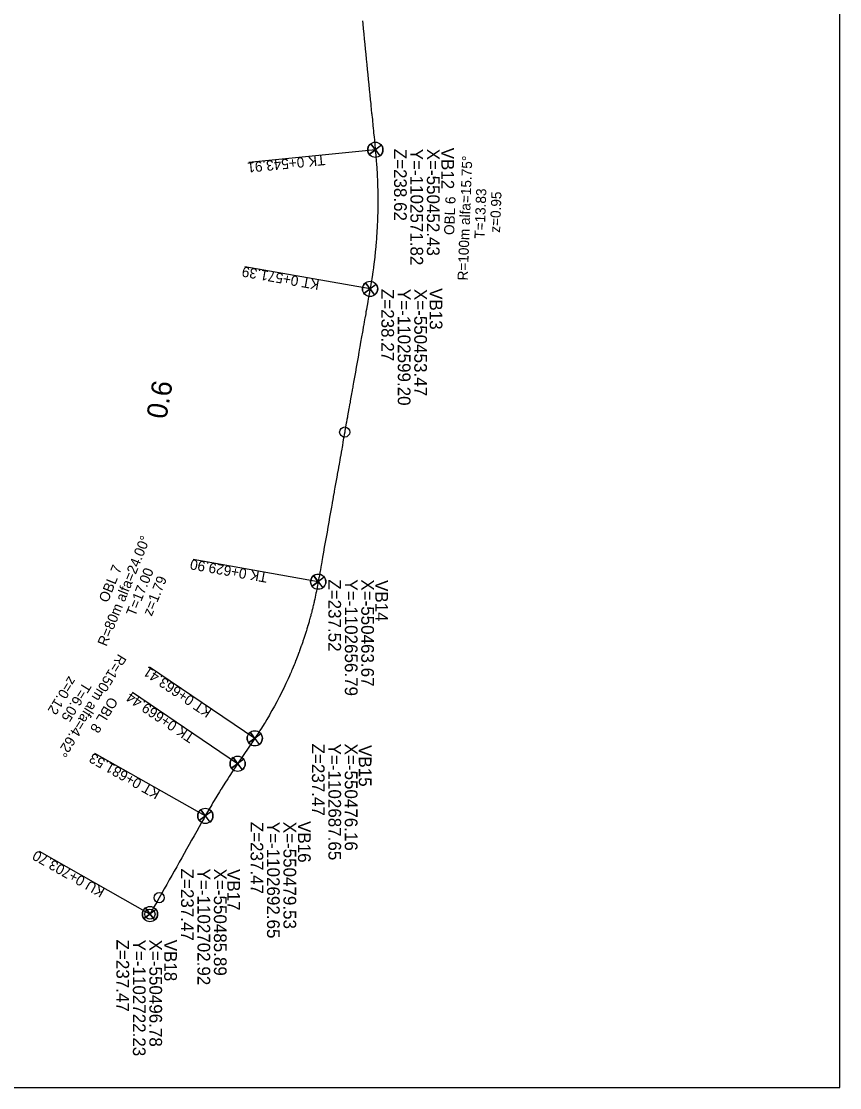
# Model space of a CAD drawing. Extents: x -583517 to -548566, y -1166112 to -1101582.
# Drawn here: x -550522.1 to -550361.1, y -1102756.4 to -1102546.5 of the extents above; entities that cross this region are included whole.
import ezdxf

# ---------------------------------------------------------------- set-up
doc = ezdxf.new("R2010")
doc.units = 0
for name, color, linetype in [('13', 7, 'Continuous'), ('59', 7, 'Continuous'), ('8', 7, 'Continuous'), ('Body pricny rez', 7, 'Continuous'), ('Rámy', 7, 'Continuous')]:
    doc.layers.add(name, color=color, linetype=linetype)

msp = doc.modelspace()

# ---------------------------------------------------------------- linework, layer by layer
at = {"layer": '13'}
for points in [[(-550452.43, -1102571.82), (-550477.31, -1102574.31)], [(-550453.47, -1102599.2), (-550478.09, -1102594.85)], [(-550463.67, -1102656.82), (-550488.29, -1102652.46)], [(-550476.16, -1102687.65), (-550496.87, -1102673.65)], [(-550479.53, -1102692.65), (-550500.25, -1102678.65)], [(-550485.89, -1102702.92), (-550507.66, -1102690.64)], [(-550496.78, -1102722.24), (-550518.55, -1102709.95)]]:
    msp.add_lwpolyline(points, dxfattribs=at)
at = {"layer": '8'}
for p, q in [((-550451.23, -1102570.93), (-550453.64, -1102572.72)), ((-550453.33, -1102570.62), (-550451.54, -1102573.03)), ((-550452.43, -1102571.82), (-550453.33, -1102570.62)), ((-550452.43, -1102571.82), (-550453.33, -1102570.62)), ((-550451.23, -1102570.93), (-550452.43, -1102571.82)), ((-550453.64, -1102572.72), (-550452.43, -1102571.82)), ((-550453.64, -1102572.72), (-550452.43, -1102571.82)), ((-550452.43, -1102571.82), (-550451.54, -1102573.03)), ((-550452.27, -1102598.31), (-550454.67, -1102600.1)), ((-550454.36, -1102598), (-550452.57, -1102600.41)), ((-550453.47, -1102599.2), (-550454.36, -1102598)), ((-550453.47, -1102599.2), (-550454.36, -1102598)), ((-550452.26, -1102598.31), (-550453.47, -1102599.2)), ((-550454.67, -1102600.1), (-550453.47, -1102599.2)), ((-550454.67, -1102600.1), (-550453.47, -1102599.2)), ((-550453.47, -1102599.2), (-550452.57, -1102600.41)), ((-550462.47, -1102655.92), (-550464.88, -1102657.71)), ((-550464.88, -1102657.71), (-550463.67, -1102656.82)), ((-550464.88, -1102657.71), (-550463.67, -1102656.82)), ((-550464.57, -1102655.61), (-550462.78, -1102658.02)), ((-550463.67, -1102656.82), (-550464.57, -1102655.61)), ((-550463.67, -1102656.82), (-550464.57, -1102655.61)), ((-550462.47, -1102655.92), (-550463.67, -1102656.82)), ((-550463.67, -1102656.82), (-550462.78, -1102658.02)), ((-550474.95, -1102686.76), (-550477.36, -1102688.54)), ((-550477.05, -1102686.45), (-550475.26, -1102688.85)), ((-550476.16, -1102687.65), (-550477.05, -1102686.45)), ((-550476.16, -1102687.65), (-550477.05, -1102686.45)), ((-550474.95, -1102686.75), (-550476.16, -1102687.65)), ((-550477.36, -1102688.55), (-550476.16, -1102687.65)), ((-550477.36, -1102688.55), (-550476.16, -1102687.65)), ((-550476.16, -1102687.65), (-550475.26, -1102688.85)), ((-550480.74, -1102693.54), (-550479.53, -1102692.65)), ((-550480.74, -1102693.54), (-550479.53, -1102692.65)), ((-550478.33, -1102691.75), (-550480.73, -1102693.54)), ((-550480.43, -1102691.44), (-550478.64, -1102693.85)), ((-550479.53, -1102692.65), (-550480.43, -1102691.44)), ((-550479.53, -1102692.65), (-550480.43, -1102691.44)), ((-550478.33, -1102691.75), (-550479.53, -1102692.65)), ((-550479.53, -1102692.65), (-550478.64, -1102693.85)), ((-550486.78, -1102701.72), (-550484.99, -1102704.13)), ((-550485.89, -1102702.92), (-550486.78, -1102701.72)), ((-550485.89, -1102702.92), (-550486.78, -1102701.72)), ((-550484.68, -1102702.03), (-550487.09, -1102703.82)), ((-550487.09, -1102703.82), (-550485.89, -1102702.92)), ((-550487.09, -1102703.82), (-550485.89, -1102702.92)), ((-550484.68, -1102702.03), (-550485.89, -1102702.92)), ((-550485.89, -1102702.92), (-550484.99, -1102704.13)), ((-550495.58, -1102721.34), (-550497.98, -1102723.13)), ((-550497.98, -1102723.13), (-550496.78, -1102722.24)), ((-550497.98, -1102723.13), (-550496.78, -1102722.24)), ((-550496.78, -1102722.24), (-550497.68, -1102721.03)), ((-550496.78, -1102722.24), (-550497.68, -1102721.03)), ((-550497.67, -1102721.03), (-550495.89, -1102723.44)), ((-550495.58, -1102721.34), (-550496.78, -1102722.24)), ((-550496.78, -1102722.24), (-550495.88, -1102723.44))]:
    msp.add_line(p, q, dxfattribs=at)
for centre in [(-550452.43, -1102571.82), (-550453.47, -1102599.2), (-550463.67, -1102656.82), (-550476.16, -1102687.65), (-550479.53, -1102692.65), (-550485.89, -1102702.92), (-550496.78, -1102722.24)]:
    msp.add_circle(centre, 1.5, dxfattribs=at)
for centre, start, end in [((-550452.43, -1102571.82), 126.6271, 216.6271), ((-550452.43, -1102571.82), 126.6271, 216.6271), ((-550452.43, -1102571.82), 306.6271, 36.6271), ((-550453.47, -1102599.2), 126.6271, 216.6271), ((-550453.47, -1102599.2), 126.6271, 216.6271), ((-550453.47, -1102599.2), 306.6271, 36.6271), ((-550463.67, -1102656.82), 126.6271, 216.6271), ((-550463.67, -1102656.82), 126.6271, 216.6271), ((-550463.67, -1102656.82), 306.6271, 36.6271), ((-550476.16, -1102687.65), 126.6271, 216.6271), ((-550476.16, -1102687.65), 126.6271, 216.6271), ((-550476.16, -1102687.65), 306.6271, 36.6271), ((-550479.53, -1102692.65), 126.6271, 216.6271), ((-550479.53, -1102692.65), 126.6271, 216.6271), ((-550479.53, -1102692.65), 306.6271, 36.6271), ((-550485.89, -1102702.92), 126.6271, 216.6271), ((-550485.89, -1102702.92), 126.6271, 216.6271), ((-550485.89, -1102702.92), 306.6271, 36.6271), ((-550496.78, -1102722.24), 126.6271, 216.6271), ((-550496.78, -1102722.24), 126.6271, 216.6271), ((-550496.78, -1102722.24), 306.6271, 36.6271)]:
    msp.add_arc(centre, 1.5, start, end, dxfattribs=at)
at = {"layer": 'Body pricny rez'}
msp.add_lwpolyline([(-550454.97, -1102546.43), (-550454.91, -1102547.04), (-550454.9, -1102547.17), (-550454.89, -1102547.19), (-550454.82, -1102547.9), (-550454.81, -1102548.04), (-550454.71, -1102549.03), (-550454.61, -1102550.03), (-550454.51, -1102551.02), (-550454.41, -1102552.02), (-550454.31, -1102553.01), (-550454.21, -1102554.01), (-550454.11, -1102555), (-550454.01, -1102556), (-550453.91, -1102556.99), (-550453.82, -1102557.99), (-550453.72, -1102558.98), (-550453.62, -1102559.98), (-550453.52, -1102560.97), (-550453.42, -1102561.97), (-550453.34, -1102562.73), (-550453.34, -1102562.75), (-550453.32, -1102562.96), (-550453.31, -1102563.05), (-550453.22, -1102563.96), (-550453.16, -1102564.58), (-550453.14, -1102564.79), (-550453.12, -1102564.95), (-550453.11, -1102565.09), (-550453.08, -1102565.3), (-550453.08, -1102565.36), (-550453.02, -1102565.95), (-550453, -1102566.1), (-550453, -1102566.14), (-550452.92, -1102566.91), (-550452.92, -1102566.94), (-550452.85, -1102567.69), (-550452.82, -1102567.94), (-550452.77, -1102568.47), (-550452.72, -1102568.93), (-550452.69, -1102569.25), (-550452.62, -1102569.93), (-550452.61, -1102570.02), (-550452.53, -1102570.8), (-550452.53, -1102570.83), (-550452.52, -1102570.92), (-550452.46, -1102571.58), (-550452.43, -1102571.82), (-550452.42, -1102571.92), (-550452.38, -1102572.36), (-550452.33, -1102572.91), (-550452.31, -1102573.14), (-550452.25, -1102573.91), (-550452.25, -1102573.91), (-550452.24, -1102573.93), (-550452.19, -1102574.69), (-550452.17, -1102574.91), (-550452.16, -1102575.06), (-550452.12, -1102575.65), (-550452.11, -1102575.84), (-550452.11, -1102575.9), (-550452.1, -1102576.04), (-550452.09, -1102576.19), (-550452.09, -1102576.22), (-550452.06, -1102576.72), (-550452.06, -1102576.9), (-550452.01, -1102577.9), (-550452, -1102578.15), (-550451.98, -1102578.9), (-550451.95, -1102579.9), (-550451.95, -1102580.26), (-550451.94, -1102580.9), (-550451.94, -1102581.9), (-550451.94, -1102582.38), (-550451.94, -1102582.71), (-550451.94, -1102582.9), (-550451.96, -1102583.9), (-550451.97, -1102584.49), (-550451.98, -1102584.62), (-550451.99, -1102584.9), (-550451.99, -1102585.06), (-550451.99, -1102585.06), (-550452.02, -1102585.9), (-550452.05, -1102586.61), (-550452.07, -1102586.9), (-550452.08, -1102587.19), (-550452.12, -1102587.8), (-550452.12, -1102587.9), (-550452.13, -1102588.01), (-550452.14, -1102588.1), (-550452.15, -1102588.3), (-550452.18, -1102588.72), (-550452.19, -1102588.89), (-550452.23, -1102589.47), (-550452.27, -1102589.89), (-550452.35, -1102590.82), (-550452.35, -1102590.89), (-550452.45, -1102591.88), (-550452.56, -1102592.88), (-550452.56, -1102592.93), (-550452.67, -1102593.87), (-550452.8, -1102594.86), (-550452.82, -1102595.03), (-550452.93, -1102595.85), (-550453.08, -1102596.84), (-550453.12, -1102597.12), (-550453.14, -1102597.21), (-550453.2, -1102597.63), (-550453.24, -1102597.83), (-550453.24, -1102597.87), (-550453.32, -1102598.35), (-550453.4, -1102598.82), (-550453.46, -1102599.17), (-550453.47, -1102599.2), (-550453.57, -1102599.8), (-550453.61, -1102599.99), (-550453.64, -1102600.19), (-550453.75, -1102600.79), (-550453.75, -1102600.81), (-550453.9, -1102601.63), (-550453.92, -1102601.77), (-550454.04, -1102602.45), (-550454.1, -1102602.76), (-550454.19, -1102603.27), (-550454.27, -1102603.74), (-550454.33, -1102604.09), (-550454.45, -1102604.73), (-550454.48, -1102604.9), (-550454.62, -1102605.71), (-550454.62, -1102605.72), (-550454.77, -1102606.54), (-550454.8, -1102606.69), (-550454.91, -1102607.36), (-550454.97, -1102607.68), (-550455.14, -1102608.66), (-550455.32, -1102609.65), (-550455.49, -1102610.63), (-550455.54, -1102610.88), (-550455.67, -1102611.62), (-550455.84, -1102612.6), (-550456.02, -1102613.59), (-550456.19, -1102614.57), (-550456.36, -1102615.56), (-550456.54, -1102616.54), (-550456.71, -1102617.53), (-550456.86, -1102618.33), (-550456.89, -1102618.51), (-550456.99, -1102619.06), (-550457.01, -1102619.19), (-550457.06, -1102619.5), (-550457.11, -1102619.79), (-550457.13, -1102619.9), (-550457.15, -1102619.98), (-550457.17, -1102620.09), (-550457.18, -1102620.15), (-550457.24, -1102620.48), (-550457.24, -1102620.52), (-550457.37, -1102621.25), (-550457.41, -1102621.46), (-550457.47, -1102621.8), (-550457.5, -1102621.98), (-550457.59, -1102622.45), (-550457.63, -1102622.71), (-550457.76, -1102623.43), (-550457.76, -1102623.44), (-550457.89, -1102624.17), (-550457.93, -1102624.42), (-550458.02, -1102624.9), (-550458.11, -1102625.4), (-550458.15, -1102625.63), (-550458.28, -1102626.36), (-550458.28, -1102626.39), (-550458.41, -1102627.09), (-550458.46, -1102627.37), (-550458.54, -1102627.82), (-550458.63, -1102628.36), (-550458.67, -1102628.55), (-550458.8, -1102629.28), (-550458.81, -1102629.34), (-550458.92, -1102630.01), (-550458.98, -1102630.33), (-550459.05, -1102630.74), (-550459.15, -1102631.31), (-550459.18, -1102631.47), (-550459.31, -1102632.2), (-550459.33, -1102632.3), (-550459.44, -1102632.93), (-550459.5, -1102633.28), (-550459.57, -1102633.66), (-550459.68, -1102634.27), (-550459.7, -1102634.39), (-550459.83, -1102635.12), (-550459.85, -1102635.25), (-550460.03, -1102636.23), (-550460.2, -1102637.22), (-550460.31, -1102637.86), (-550460.38, -1102638.2), (-550460.51, -1102638.99), (-550460.55, -1102639.19), (-550460.71, -1102640.08), (-550460.72, -1102640.17), (-550460.88, -1102641.05), (-550460.9, -1102641.16), (-550460.94, -1102641.37), (-550461, -1102641.75), (-550461.07, -1102642.14), (-550461.25, -1102643.13), (-550461.42, -1102644.11), (-550461.6, -1102645.1), (-550461.77, -1102646.08), (-550461.94, -1102647.07), (-550462.12, -1102648.05), (-550462.29, -1102649.04), (-550462.47, -1102650.02), (-550462.64, -1102651), (-550462.75, -1102651.64), (-550462.82, -1102651.99), (-550462.82, -1102652.03), (-550462.89, -1102652.43), (-550462.96, -1102652.82), (-550462.99, -1102652.97), (-550463.03, -1102653.21), (-550463.1, -1102653.61), (-550463.16, -1102653.92), (-550463.17, -1102653.96), (-550463.17, -1102654), (-550463.24, -1102654.39), (-550463.31, -1102654.79), (-550463.34, -1102654.94), (-550463.38, -1102655.15), (-550463.38, -1102655.18), (-550463.45, -1102655.57), (-550463.51, -1102655.93), (-550463.52, -1102655.97), (-550463.59, -1102656.36), (-550463.66, -1102656.75), (-550463.67, -1102656.82), (-550463.69, -1102656.91), (-550463.73, -1102657.15), (-550463.8, -1102657.54), (-550463.87, -1102657.9), (-550463.88, -1102657.93), (-550463.95, -1102658.33), (-550464.02, -1102658.64), (-550464.03, -1102658.72), (-550464.06, -1102658.88), (-550464.11, -1102659.11), (-550464.19, -1102659.5), (-550464.27, -1102659.86), (-550464.28, -1102659.89), (-550464.36, -1102660.28), (-550464.41, -1102660.47), (-550464.45, -1102660.67), (-550464.49, -1102660.83), (-550464.54, -1102661.06), (-550464.6, -1102661.32), (-550464.63, -1102661.45), (-550464.65, -1102661.52), (-550464.72, -1102661.8), (-550464.73, -1102661.84), (-550464.74, -1102661.91), (-550464.82, -1102662.23), (-550464.84, -1102662.28), (-550464.92, -1102662.61), (-550464.96, -1102662.77), (-550465.02, -1102663), (-550465.1, -1102663.28), (-550465.12, -1102663.39), (-550465.22, -1102663.74), (-550465.23, -1102663.77), (-550465.31, -1102664.08), (-550465.33, -1102664.16), (-550465.33, -1102664.16), (-550465.36, -1102664.27), (-550465.36, -1102664.27), (-550465.36, -1102664.27), (-550465.37, -1102664.28), (-550465.44, -1102664.54), (-550465.45, -1102664.57), (-550465.48, -1102664.71), (-550465.55, -1102664.93), (-550465.55, -1102664.94), (-550465.66, -1102665.31), (-550465.76, -1102665.67), (-550465.77, -1102665.7), (-550465.82, -1102665.87), (-550465.89, -1102666.08), (-550466, -1102666.46), (-550466.05, -1102666.62), (-550466.12, -1102666.84), (-550466.24, -1102667.22), (-550466.36, -1102667.58), (-550466.37, -1102667.6), (-550466.38, -1102667.64), (-550466.49, -1102667.98), (-550466.67, -1102668.52), (-550466.69, -1102668.57), (-550466.73, -1102668.7), (-550466.75, -1102668.74), (-550466.76, -1102668.79), (-550466.78, -1102668.83), (-550466.98, -1102669.41), (-550467, -1102669.47), (-550467.34, -1102670.41), (-550467.45, -1102670.71), (-550467.46, -1102670.74), (-550467.53, -1102670.93), (-550467.61, -1102671.16), (-550467.69, -1102671.35), (-550467.82, -1102671.69), (-550467.93, -1102671.98), (-550468.04, -1102672.25), (-550468.04, -1102672.26), (-550468.05, -1102672.28), (-550468.29, -1102672.89), (-550468.42, -1102673.21), (-550468.81, -1102674.13), (-550468.91, -1102674.36), (-550469.01, -1102674.61), (-550469.13, -1102674.87), (-550469.15, -1102674.91), (-550469.15, -1102674.92), (-550469.16, -1102674.94), (-550469.2, -1102675.05), (-550469.33, -1102675.33), (-550469.61, -1102675.96), (-550469.61, -1102675.96), (-550469.77, -1102676.31), (-550470.03, -1102676.87), (-550470.46, -1102677.77), (-550470.57, -1102677.99), (-550470.9, -1102678.67), (-550471.36, -1102679.56), (-550471.41, -1102679.65), (-550471.82, -1102680.45), (-550472.28, -1102681.29), (-550472.3, -1102681.33), (-550472.78, -1102682.2), (-550473.19, -1102682.92), (-550473.28, -1102683.07), (-550473.79, -1102683.93), (-550474.14, -1102684.52), (-550474.31, -1102684.78), (-550474.84, -1102685.63), (-550475.13, -1102686.1), (-550475.38, -1102686.47), (-550475.93, -1102687.31), (-550476.16, -1102687.65), (-550476.49, -1102688.14), (-550477.05, -1102688.97), (-550477.61, -1102689.79), (-550478.17, -1102690.62), (-550478.72, -1102691.45), (-550479.28, -1102692.28), (-550479.53, -1102692.65), (-550479.84, -1102693.11), (-550480.4, -1102693.94), (-550480.95, -1102694.78), (-550481.2, -1102695.17), (-550481.49, -1102695.62), (-550482.03, -1102696.46), (-550482.56, -1102697.31), (-550482.77, -1102697.66), (-550482.81, -1102697.72), (-550483.08, -1102698.16), (-550483.6, -1102699.01), (-550484.12, -1102699.87), (-550484.38, -1102700.31), (-550484.63, -1102700.73), (-550485.13, -1102701.6), (-550485.63, -1102702.46), (-550485.89, -1102702.92), (-550486.12, -1102703.33), (-550486.61, -1102704.21), (-550487.1, -1102705.08), (-550487.59, -1102705.95), (-550488.08, -1102706.82), (-550488.58, -1102707.69), (-550489.07, -1102708.56), (-550489.56, -1102709.43), (-550490.05, -1102710.3), (-550490.54, -1102711.17), (-550491.03, -1102712.04), (-550491.52, -1102712.92), (-550492.01, -1102713.79), (-550492.51, -1102714.66), (-550493, -1102715.53), (-550493, -1102715.53), (-550493.49, -1102716.4), (-550493.98, -1102717.27), (-550494.47, -1102718.14), (-550494.96, -1102719.01), (-550495.45, -1102719.88), (-550495.94, -1102720.75), (-550496.44, -1102721.63), (-550496.78, -1102722.23)], dxfattribs=at)
for centre in [(-550458.46, -1102627.37), (-550494.96, -1102719.01), (-550496.78, -1102722.24)]:
    msp.add_circle(centre, 1, dxfattribs=at)
at = {"layer": 'Rámy'}
msp.add_lwpolyline([(-550658.05, -1102021.4), (-550658.05, -1102756.4), (-550361.05, -1102756.4), (-550361.05, -1102021.4)], close=True, dxfattribs=at)

# ---------------------------------------------------------------- texts
at = {"layer": '13'}
for s, height, rotation, p in [('TK 0+543.91', 2, 185.7064, (-550462.38, -1102572.82)), ('R=100m alfa=15.75%%d', 2, 87.8319, (-550434.26, -1102597.57)), ('  T=13.83', 2, 87.8319, (-550431, -1102590.83)), ('OBL 6', 2, 87.8319, (-550436.92, -1102588.62)), ('   z=0.95', 2, 87.8319, (-550427.98, -1102590.4)), ('KT 0+571.39', 2, 169.9574, (-550463.32, -1102597.46)), ('0.6', 4, 79.9574, (-550493.58, -1102624.97)), ('R=80m alfa=24.00%%d', 2, 67.9574, (-550505.33, -1102669.68)), ('OBL 7', 2, 67.9574, (-550505.08, -1102661.08)), ('TK 0+629.90', 2, 169.9574, (-550473.52, -1102655.07)), ('  T=17.00', 2, 67.9574, (-550500.26, -1102665.17)), ('   z=1.79', 2, 67.9574, (-550497.28, -1102665.8)), ('R=150m alfa=4.62%%d', 2, 238.2661, (-550502.98, -1102670.9)), ('KT 0+663.41', 2, 145.9573, (-550484.44, -1102682.05)), ('   z=0.12', 2, 238.2661, (-550511.57, -1102673.39)), ('  T=6.05', 2, 238.2661, (-550509.13, -1102675.16)), ('TK 0+669.44', 2, 145.9573, (-550487.82, -1102687.05)), ('OBL 8', 2, 238.2661, (-550504.67, -1102679.34)), ('KT 0+681.53', 2, 150.5749, (-550494.6, -1102698.01)), ('KU 0+703.70', 2, 150.5749, (-550505.49, -1102717.32))]:
    msp.add_text(s, height=height, rotation=rotation, dxfattribs=at).set_placement(p)
at = {"layer": '59'}
for s, p in [('VB12', (-550439.43, -1102571.4)), ('Z=238.62', (-550448.75, -1102571.61)), ('Y=-1102571.82', (-550445.52, -1102571.61)), ('X=-550452.43', (-550442.28, -1102571.61)), ('Z=238.27', (-550451.25, -1102599.2)), ('Y=-1102599.20', (-550448.01, -1102599.2)), ('X=-550453.47', (-550444.77, -1102599.2)), ('VB13', (-550441.73, -1102599.04)), ('Z=237.52', (-550461.67, -1102656.36)), ('Y=-1102656.79', (-550458.43, -1102656.36)), ('X=-550463.67', (-550455.2, -1102656.36)), ('VB14', (-550452.43, -1102656.5)), ('Z=237.47', (-550464.91, -1102688.69)), ('Y=-1102687.65', (-550461.67, -1102688.69)), ('X=-550476.16', (-550458.44, -1102688.69)), ('VB15', (-550455.68, -1102688.98)), ('Z=237.47', (-550476.98, -1102704.07)), ('Y=-1102692.65', (-550473.75, -1102704.07)), ('X=-550479.53', (-550470.51, -1102704.07)), ('VB16', (-550467.65, -1102703.93)), ('Z=237.47', (-550490.67, -1102713.29)), ('Y=-1102702.92', (-550487.43, -1102713.29)), ('X=-550485.89', (-550484.2, -1102713.29)), ('VB17', (-550481.55, -1102713.38)), ('Z=237.47', (-550503.38, -1102727.26)), ('Y=-1102722.23', (-550500.14, -1102727.26)), ('X=-550496.78', (-550496.9, -1102727.26)), ('VB18', (-550493.98, -1102727.28))]:
    msp.add_text(s, height=2.5, rotation=270, dxfattribs=at).set_placement(p)

doc.saveas('drawing.dxf')
